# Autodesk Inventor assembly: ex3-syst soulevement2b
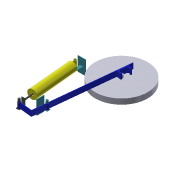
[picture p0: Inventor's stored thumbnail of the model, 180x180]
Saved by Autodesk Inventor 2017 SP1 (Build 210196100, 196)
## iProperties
Part Number: ex3-syst soulevement2b
Material: Générique
Document SubType Name: Assembly
Designer: TJ
Author: TJ
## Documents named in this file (6)
- H:\Consmec\TSsi\02-Cours\02-02-Cinematique\02-02-02-Cinematique graphique\02-02-02-03-Composition des Vitesses\02-02-02-03-02-Exercices compo des Vitesses\02-02-02-03-02-03-Exercice3CompVit\ex3-syst soulevement2b.iam
- H:\Consmec\TSsi\02-Cours\02-02-Cinematique\02-02-02-Cinematique graphique\02-02-02-03-Composition des Vitesses\02-02-02-03-02-Exercices compo des Vitesses\02-02-02-03-02-03-Exercice3CompVit\Pièce5.ipt
- H:\Consmec\TSsi\02-Cours\02-02-Cinematique\02-02-02-Cinematique graphique\02-02-02-03-Composition des Vitesses\02-02-02-03-02-Exercices compo des Vitesses\02-02-02-03-02-03-Exercice3CompVit\Pièce3.ipt
- H:\Consmec\TSsi\02-Cours\02-02-Cinematique\02-02-02-Cinematique graphique\02-02-02-03-Composition des Vitesses\02-02-02-03-02-Exercices compo des Vitesses\02-02-02-03-02-03-Exercice3CompVit\Pièce4.ipt
- H:\Consmec\TSsi\02-Cours\02-02-Cinematique\02-02-02-Cinematique graphique\02-02-02-03-Composition des Vitesses\02-02-02-03-02-Exercices compo des Vitesses\02-02-02-03-02-03-Exercice3CompVit\Pièce2.ipt
- H:\Consmec\TSsi\02-Cours\02-02-Cinematique\02-02-02-Cinematique graphique\02-02-02-03-Composition des Vitesses\02-02-02-03-02-Exercices compo des Vitesses\02-02-02-03-02-03-Exercice3CompVit\Pièce1.ipt
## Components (6 placed, 5 different names)
1. Pièce5:1 — Logement:1, Angle:2, Angle:3
2. Pièce5:2 — Logement:3, Angle:3
3. Pièce3:1 — Logement:1, Placage:1, Angle:1
4. Pièce4:1 — Placage:1, Angle:1, Logement:2, Angle:2
5. Pièce2:1 — Logement:2, Logement:3, Logement:4
6. Pièce1:1 — Logement:4
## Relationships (8: Insert 4, Angle 3, Mate 1)
- Logement:1 [Insert]: Pièce5:1 ↔ Pièce3:1
- Placage:1 [Mate]: Pièce3:1 ↔ Pièce4:1
- Angle:1: Pièce3:1 ↔ Pièce4:1
- Logement:2 [Insert]: Pièce4:1 ↔ Pièce2:1
- Angle:2: Pièce5:1 ↔ Pièce4:1
- Logement:3 [Insert]: Pièce5:2 ↔ Pièce2:1
- Angle:3: Pièce5:1 ↔ Pièce5:2
- Logement:4 [Insert]: Pièce2:1 ↔ Pièce1:1
